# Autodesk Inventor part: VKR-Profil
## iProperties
Created: 2001-12
Part Number: VKR-Profil
Material: Steel, Mild
Description: VKR 75x75x3_440
Document SubType Name: Modeling
Designer: Tobben
Control State: 0
Master: False
Checked Out: False
Shininess: 64.0
Length Units: 11269
Angle Units: 11279
Time Units: 11290
Mass Units: 11283
Length Display Precision: 3
Angle Display Precision: 2
Density: 0.0
Volumn: 0.0
Area: 0.0
PropertySet Name: Model Information
Author: Tobben
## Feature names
1. Derived Body1 [Tagging]
